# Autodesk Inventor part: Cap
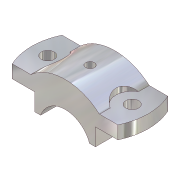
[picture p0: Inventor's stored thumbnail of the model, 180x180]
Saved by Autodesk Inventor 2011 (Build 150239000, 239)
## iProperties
Shininess: 77.0
Length Units: 11269
Angle Units: 11279
Time Units: 11290
Mass Units: 11283
Length Display Precision: 3
Angle Display Precision: 2
Created: 2002-02
Part Number: Cap
Document SubType Name: Modeling
Designer: ***
Density: 1 g/cm^3
Density: 0.0
Volumn: 0.0
Area: 0.0
PropertySet Name: Model Information
Control State: 0
Master: False
Checked Out: False
Author: ***
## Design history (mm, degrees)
sketch "Sketch2"
  geometry: L1 (22.656, 22.99)-(28.029, 22.99); L2 (28.029, 22.99)-(28.029, 38.99); L3 (28.029, 38.99)-(54.029, 38.99); L4 (54.029, 38.99)-(54.029, 50.99); L5 (54.029, 50.99)-(31.778, 50.99); L6 (-22.599, 22.99)-(-27.971, 22.99); L7 (-27.971, 22.99)-(-27.971, 38.99); L8 (-27.971, 38.99)-(-53.971, 38.99); L9 (-53.971, 38.99)-(-53.971, 50.99); L10 (-53.971, 50.99)-(-31.72, 50.99); A1 r 24 centre (0.029, 14.99) between (22.656, 22.99) and (-22.599, 22.99); A2 r 48 centre (0.029, 14.99) between (31.778, 50.99) and (-31.72, 50.99)
  constraints: 20 end point, 5 equal length, 4 parallel, 4 perpendicular, 4 point on circle, 2 centre point, 1 coincident, 1 horizontal, 1 point on line
  dimensions: "d0" = 24 radius of A1; "d1" = 8 distance from line of L1 A1.centre; "d2" = 12 distance of L8.end L9.end; "d3" = 16 distance of L6.end L7.end; "d4" = 48 radius of A2; "d5" = 108 distance between parallel lines of L9 L4; "d6" = 56 distance between parallel lines of L7 L2
extrude "Extrusion1" new body sketch "Sketch2" stored distance "d7" = 46; taper "d8" = 0 deg
sketch "Sketch3"
  geometry: L1 (17.108, 0)-(40.349, 0); L2 (40.349, 0)-(40.349, -46); L3 (40.349, -46)-(17.108, -46); L4 (0, -46)-(22.251, -46) reference; L5 (22.251, 0)-(0, 0) reference; L6 (22.251, 0)-(22.251, -46) reference; A1 r 54 centre (-31.749, -23) between (17.108, -46) and (17.108, 0)
  constraints: 6 end point, 2 collinear, 2 point on circle, 1 centre point, 1 horizontal, 1 parallel, 1 perpendicular, 1 vertical alignment
  dimensions: "d9" = 54 radius of A1; "d10" = 54 distance from line of L6 A1.centre
extrude "Extrusion2" cut sketch "Sketch3" stored distance "d11" = 46; taper "d12" = 0 deg
sketch "Sketch4"
  geometry: L1 (17.108, 46)-(0, 46) reference; A1 r 54 centre (-31.749, 23) between (17.108, 0) and (17.108, 46) reference; 1 further point
  dimensions: "d13" = 23 distance from line of L1 point (7.251, 23); "d14" = 39 distance of A1.centre point (7.251, 23)
hole "Hole1" sketch "Sketch4" diameter "d15" = 30; stored, may be unused: countersink angle "d19" = 82 deg, drill point angle "d21" = 118 deg; dims "d16" = 6, "d17" = 4, "d18" = 2, "d20" = 8
hole "Hole2" sketch "Sketch4" diameter "d22" = 12; stored, may be unused: countersink angle "d26" = 82 deg, drill point angle "d28" = 118 deg; dims "d23" = 6, "d24" = 4, "d25" = 2, "d27" = 8
workplane "Work Plane1"
mirror "Mirror1"
workplane "Work Plane2"
sketch "Sketch5"
  geometry: L1 (31.749, -23)-(-31.749, -23) reference; C1 r 6 at (39, 0) reference; 1 further point
  dimensions: "d30" = 23 distance from line of L1 point (0, 0); "d31" = 39 distance of C1.centre point (0, 0)
hole "Hole3" sketch "Sketch5" at (0, 0) diameter "d32" = 6; stored, may be unused: countersink angle "d36" = 82 deg, drill point angle "d38" = 118 deg; dims "d33" = 6, "d34" = 8, "d35" = 16, "d37" = 8
body "Solid1"
other parameters: "d29" = -54
